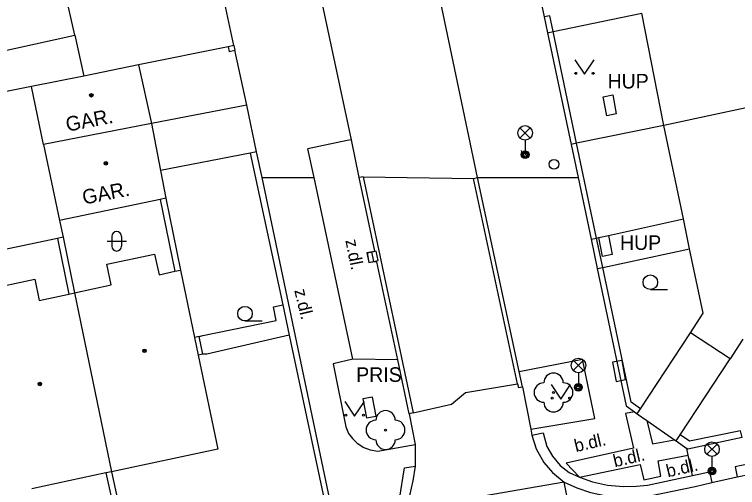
# Model space of a CAD drawing. Extents: x -596229 to -595156, y -1161237 to -1159376.
# Drawn here: x -595834.73 to -595797.54, y -1160999.35 to -1160975 of the extents above; entities that cross this region are included whole.
import ezdxf

# ---------------------------------------------------------------- set-up
doc = ezdxf.new("R2010")
doc.units = 0
for name, color, linetype in [('DOP - kresba z DSPS bez souradnic', 7, 'Continuous'), ('DOP - rozhrani ploch obecne', 7, 'Continuous'), ('Level 22', 7, 'Continuous'), ('Level 24', 7, 'Continuous'), ('Level 27', 7, 'Continuous'), ('Level 28', 7, 'Continuous'), ('Level 33', 7, 'Continuous'), ('Level 36', 7, 'Continuous'), ('Level 39', 7, 'Continuous'), ('plynovod - povrch.  znaky - PRIS skut. velikost', 7, 'Continuous'), ('Specificka linie pasportu komunikaci', 7, 'Continuous'), ('TM - budovy zdene_ betonove - VP', 7, 'Continuous'), ('TM - chodniky - VP', 7, 'Continuous'), ('TM - komunikace - VP', 7, 'Continuous'), ('TM - letecke snimky - pomocna linie', 7, 'Continuous'), ('TM - plot drateny_ kovovy - VP', 7, 'Continuous'), ('TM - podezdivka plotu - VP', 7, 'Continuous'), ('TM - popis objektu', 7, 'Continuous'), ('TM - popis povrchu', 7, 'Continuous'), ('TM - rozhrani mezi zpev. plochami mezi sebou - VP', 7, 'Continuous'), ('TM - rozhrani ploch obecne - VP', 7, 'Continuous'), ('TM - vjezd na pozemek', 7, 'Continuous'), ('TM - zabradli - VP', 7, 'Continuous')]:
    doc.layers.add(name, color=color, linetype=linetype)

msp = doc.modelspace()

# ---------------------------------------------------------------- linework, layer by layer
at = {"layer": 'DOP - kresba z DSPS bez souradnic'}
msp.add_lwpolyline([(-595832.52, -1160986.53), (-595831.93, -1160989.39)], dxfattribs=at)
at = {"layer": 'DOP - rozhrani ploch obecne'}
for points in [[(-595833.85, -1160978.71), (-595835.23, -1160978.99)], [(-595832.41, -1160985.61), (-595832.23, -1160986.47)], [(-595832.52, -1160986.53), (-595837.52, -1160987.57)], [(-595832.23, -1160986.47), (-595832.52, -1160986.53)], [(-595832.23, -1160986.47), (-595831.64, -1160989.33)]]:
    msp.add_lwpolyline(points, dxfattribs=at)
at = {"layer": 'Level 22'}
for centre in [(-595807, -1160994.46), (-595815.64, -1160996.39)]:
    msp.add_circle(centre, 0.05, dxfattribs=at)
for centre, start, end in [((-595807, -1160993.96), 0, 180), ((-595807.5, -1160994.46), 90, 270), ((-595806.5, -1160994.46), 270, 90), ((-595807, -1160994.96), 180, 0), ((-595815.64, -1160995.89), 0, 180), ((-595816.14, -1160996.39), 90, 270), ((-595815.14, -1160996.39), 270, 90), ((-595815.64, -1160996.89), 180, 0)]:
    msp.add_arc(centre, 0.5, start, end, dxfattribs=at)
at = {"layer": 'Level 24'}
for points in [[(-595803.968, -1160992.905), (-595803.783, -1160993.888), (-595803.292, -1160993.795), (-595803.477, -1160992.812)], [(-595816.809, -1160994.786), (-595816.622, -1160995.768), (-595816.13, -1160995.674), (-595816.318, -1160994.692)]]:
    msp.add_lwpolyline(points, close=True, dxfattribs=at)
at = {"layer": 'Level 27'}
msp.add_line((-595816.36, -1160987.225), (-595816.26, -1160987.715), dxfattribs=at)
msp.add_lwpolyline([(-595816.605, -1160987.275), (-595816.505, -1160987.765), (-595816.015, -1160987.665), (-595816.115, -1160987.175)], close=True, dxfattribs=at)
at = {"layer": 'Level 28'}
msp.add_circle((-595806.98, -1160982.71), 0.25, dxfattribs=at)
at = {"layer": 'Level 33'}
for p, q in [((-595808.725, -1160981.36), (-595808.195, -1160980.83)), ((-595808.725, -1160980.83), (-595808.195, -1160981.36)), ((-595808.46, -1160981.47), (-595808.46, -1160982.22)), ((-595805.985, -1160993.33), (-595805.455, -1160992.8)), ((-595805.985, -1160992.8), (-595805.455, -1160993.33)), ((-595805.72, -1160993.44), (-595805.72, -1160994.19)), ((-595799.115, -1160997.64), (-595798.585, -1160997.11)), ((-595799.115, -1160997.11), (-595798.585, -1160997.64)), ((-595798.85, -1160997.75), (-595798.85, -1160998.5))]:
    msp.add_line(p, q, dxfattribs=at)
for centre, radius in [((-595808.46, -1160981.095), 0.375), ((-595808.46, -1160982.22), 0.2), ((-595808.46, -1160982.22), 0.145), ((-595808.46, -1160982.22), 0.0876), ((-595805.72, -1160993.065), 0.375), ((-595805.72, -1160994.19), 0.2), ((-595805.72, -1160994.19), 0.145), ((-595805.72, -1160994.19), 0.0876), ((-595798.85, -1160997.375), 0.375), ((-595798.85, -1160998.5), 0.2), ((-595798.85, -1160998.5), 0.145), ((-595798.85, -1160998.5), 0.0876)]:
    msp.add_circle(centre, radius, dxfattribs=at)
at = {"layer": 'Level 36'}
for p, q in [((-595829.716, -1160986.426), (-595829.716, -1160986.926)), ((-595829.216, -1160986.426), (-595829.216, -1160986.926)), ((-595829.966, -1160986.676), (-595828.966, -1160986.676)), ((-595802.02, -1160989.155), (-595801.145, -1160989.155)), ((-595822.87, -1160990.775), (-595821.995, -1160990.775))]:
    msp.add_line(p, q, dxfattribs=at)
for points in [[(-595805.91, -1160977.33), (-595805.41, -1160978.08), (-595804.91, -1160977.33)], [(-595807.12, -1160994.05), (-595806.62, -1160994.8), (-595806.12, -1160994.05)], [(-595817.73, -1160994.92), (-595817.23, -1160995.67), (-595816.73, -1160994.92)]]:
    msp.add_lwpolyline(points, dxfattribs=at)
for centre, radius in [((-595805.86, -1160978.03), 0.05), ((-595804.961, -1160978.03), 0.05), ((-595802.02, -1160988.78), 0.375), ((-595822.87, -1160990.4), 0.375), ((-595807.07, -1160994.75), 0.05), ((-595806.171, -1160994.75), 0.05), ((-595817.68, -1160995.62), 0.05), ((-595816.781, -1160995.62), 0.05)]:
    msp.add_circle(centre, radius, dxfattribs=at)
for centre, start, end in [((-595829.466, -1160986.426), 0, 180), ((-595829.466, -1160986.926), 180, 0)]:
    msp.add_arc(centre, 0.25, start, end, dxfattribs=at)
at = {"layer": 'Level 39'}
for centre, radius in [((-595830.77, -1160979.16), 0.09), ((-595830.77, -1160979.16), 0.0398), ((-595830.03, -1160982.66), 0.09), ((-595830.03, -1160982.66), 0.0398), ((-595828.04, -1160992.31), 0.09), ((-595828.04, -1160992.31), 0.0398), ((-595833.42, -1160994.02), 0.09), ((-595833.42, -1160994.02), 0.0398)]:
    msp.add_circle(centre, radius, dxfattribs=at)
at = {"layer": 'plynovod - povrch.  znaky - PRIS skut. velikost'}
for points in [[(-595804.26, -1160980.22), (-595804.44, -1160979.24), (-595803.95, -1160979.14), (-595803.77, -1160980.12), (-595804.26, -1160980.22)], [(-595804.67, -1160986.48), (-595804.18, -1160986.38)], [(-595804.48, -1160987.46), (-595804.67, -1160986.48)], [(-595804.18, -1160986.38), (-595803.99, -1160987.36), (-595804.48, -1160987.46)]]:
    msp.add_lwpolyline(points, dxfattribs=at)
at = {"layer": 'Specificka linie pasportu komunikaci'}
for points in [[(-595821.99, -1160983.4), (-595819.31, -1160983.4)], [(-595816.79, -1160983.36), (-595811.11, -1160983.44)], [(-595810.91, -1160983.4), (-595810.37, -1160983.4), (-595807.43, -1160983.4), (-595805.74, -1160983.4)], [(-595804.18, -1160986.38), (-595800.32, -1160985.52)], [(-595805.07, -1160986.57), (-595804.79, -1160986.51)], [(-595804.79, -1160986.51), (-595804.67, -1160986.48)], [(-595804.47, -1160988.02), (-595800, -1160987.06)], [(-595804.76, -1160988.08), (-595804.47, -1160988.02)], [(-595814.22, -1160995.5), (-595812.25, -1160995.06), (-595811.52, -1160994.45), (-595808.85, -1160994.02)], [(-595799.85, -1160998.73), (-595800, -1160998.014), (-595800.07, -1160997.68)], [(-595806.45, -1160999.08), (-595814.68, -1161000.49)], [(-595804.43, -1161009.24), (-595806.45, -1160999.08)]]:
    msp.add_lwpolyline(points, dxfattribs=at)
at = {"layer": 'TM - budovy zdene_ betonove - VP'}
for points in [[(-595831.63, -1160976.06), (-595832.12, -1160973.85)], [(-595801.32, -1160980.71), (-595802.46, -1160974.93)], [(-595835.68, -1160976.96), (-595831.63, -1160976.06)], [(-595828.35, -1160977.6), (-595831.16, -1160978.17)], [(-595828.35, -1160977.6), (-595827.68, -1160980.62)], [(-595831.16, -1160978.17), (-595833.85, -1160978.71)], [(-595833.23, -1160981.7), (-595833.85, -1160978.71)], [(-595792.7, -1160978.87), (-595801.32, -1160980.71)], [(-595827.68, -1160980.62), (-595833.23, -1160981.7)], [(-595827.68, -1160980.62), (-595827.21, -1160983.03)], [(-595800.32, -1160985.52), (-595801.32, -1160980.71)], [(-595833.23, -1160981.7), (-595832.41, -1160985.61)], [(-595827.21, -1160983.03), (-595826.94, -1160984.46)], [(-595827.23, -1160984.52), (-595832.41, -1160985.61)], [(-595826.94, -1160984.46), (-595827.23, -1160984.52)], [(-595800, -1160987.06), (-595800.32, -1160985.52)], [(-595799.31, -1160990.38), (-595800, -1160987.06)], [(-595829.97, -1160987.85), (-595827.52, -1160987.34)], [(-595827.52, -1160987.34), (-595827.29, -1160988.4)], [(-595829.75, -1160988.92), (-595829.97, -1160987.85)], [(-595827.29, -1160988.4), (-595826.47, -1160988.22)], [(-595826.47, -1160988.22), (-595826.18, -1160988.16)], [(-595826.18, -1160988.16), (-595825.46, -1160991.62)], [(-595836.26, -1160989.17), (-595833.68, -1160988.63)], [(-595833.68, -1160988.63), (-595833.45, -1160989.72)], [(-595831.64, -1160989.33), (-595829.75, -1160988.92)], [(-595833.45, -1160989.72), (-595831.93, -1160989.39)], [(-595831.93, -1160989.39), (-595831.64, -1160989.33)], [(-595831.64, -1160989.33), (-595829.73, -1160998.54)], [(-595799.96, -1160991.39), (-595799.31, -1160990.38)], [(-595797.91, -1160992.72), (-595799.96, -1160991.39)], [(-595825.46, -1160991.62), (-595825.27, -1160992.53)], [(-595797.26, -1160991.72), (-595797.91, -1160992.72)], [(-595825.27, -1160992.53), (-595824.27, -1160997.38)], [(-595824.27, -1160997.38), (-595829.73, -1160998.54)], [(-595830.02, -1160998.6), (-595833.84, -1160999.41)], [(-595829.73, -1160998.54), (-595830.02, -1160998.6)]]:
    msp.add_lwpolyline(points, dxfattribs=at)
at = {"layer": 'TM - chodniky - VP'}
for points in [[(-595822.78, -1160979.67), (-595823.39, -1160976.84)], [(-595822.27, -1160982.07), (-595822.78, -1160979.67)], [(-595802.52, -1160995.3), (-595799.96, -1160991.39)], [(-595817.33, -1160992.75), (-595818.34, -1160992.98), (-595817.68, -1160996.23), (-595817.54, -1160996.57), (-595817.34, -1160996.83), (-595817.1, -1160997.06), (-595816.75, -1160997.29), (-595816.43, -1160997.41), (-595816.04, -1160997.48), (-595814.11, -1160997.13)], [(-595808.16, -1160996.35), (-595804.88, -1160995.8), (-595805.51, -1160992.75)], [(-595800.49, -1160996.63), (-595797.91, -1160992.72)], [(-595802.69, -1160995.55), (-595802.52, -1160995.3)], [(-595800.7, -1160996.95), (-595800.49, -1160996.63)]]:
    msp.add_lwpolyline(points, dxfattribs=at)
at = {"layer": 'TM - komunikace - VP'}
for points in [[(-595817.4, -1160981.45), (-595819.2, -1160973.01)], [(-595810.91, -1160983.4), (-595812.97, -1160973.56)], [(-595817.4, -1160981.45), (-595817.61, -1160981.49), (-595819.63, -1160981.91)], [(-595819.31, -1160983.4), (-595819.63, -1160981.91)], [(-595817.33, -1160992.75), (-595819.31, -1160983.4)], [(-595808.76, -1160993.38), (-595810.91, -1160983.4)], [(-595815.01, -1160992.78), (-595817.33, -1160992.75)], [(-595814.43, -1160995.55), (-595815.01, -1160992.78)], [(-595808.59, -1160994.16), (-595808.76, -1160993.38)], [(-595808.59, -1160994.16), (-595808.16, -1160996.35)], [(-595814.43, -1160995.55), (-595814.11, -1160997.13)], [(-595808.16, -1160996.35), (-595808.11, -1160996.65)], [(-595808.11, -1160996.65), (-595807.89, -1160997.35), (-595807.5, -1160998.06), (-595807.06, -1160998.58), (-595806.45, -1160999.08)], [(-595814.11, -1160997.13), (-595814.12, -1160998.25)], [(-595797.56, -1160998.79), (-595796.89, -1160998.66), (-595791.5, -1160997.54), (-595790.81, -1160997.39)], [(-595814.12, -1160998.25), (-595814.23, -1160999), (-595814.41, -1160999.76), (-595814.68, -1161000.49)], [(-595798.85, -1160999.09), (-595797.56, -1160998.79)], [(-595806.45, -1160999.08), (-595805.8, -1160999.37), (-595805.1, -1160999.6), (-595804.27, -1160999.78), (-595803.36, -1160999.86), (-595802.64, -1160999.84), (-595802.05, -1160999.77), (-595799.72, -1160999.29), (-595798.85, -1160999.09)]]:
    msp.add_lwpolyline(points, dxfattribs=at)
at = {"layer": 'TM - letecke snimky - pomocna linie'}
for points in [[(-595831.63, -1160976.06), (-595831.16, -1160978.17)], [(-595822.6, -1160982.14), (-595827.21, -1160983.03)], [(-595825.23, -1160991.57), (-595825.04, -1160991.53), (-595821.26, -1160990.76), (-595821.4, -1160990.05), (-595820.93, -1160989.95)], [(-595825.23, -1160991.57), (-595825.46, -1160991.62)], [(-595825.04, -1160992.48), (-595825.23, -1160991.57)], [(-595820.6, -1160991.51), (-595824.84, -1160992.49), (-595825.04, -1160992.48)], [(-595825.04, -1160992.48), (-595825.27, -1160992.53)], [(-595808.76, -1160993.38), (-595805.51, -1160992.75)]]:
    msp.add_lwpolyline(points, dxfattribs=at)
at = {"layer": 'TM - plot drateny_ kovovy - VP'}
for points in [[(-595807.02, -1160975.88), (-595807.19, -1160975.07), (-595807.48, -1160975.13)], [(-595805.81, -1160981.63), (-595807.02, -1160975.88)], [(-595823.73, -1160976.66), (-595823.68, -1160976.9), (-595823.39, -1160976.84)], [(-595804.79, -1160986.51), (-595805.81, -1160981.63)], [(-595822.6, -1160982.14), (-595820.93, -1160989.95)], [(-595804.47, -1160988.02), (-595804.79, -1160986.51)], [(-595802.52, -1160995.3), (-595803.01, -1160994.96), (-595804.47, -1160988.02)], [(-595820.93, -1160989.95), (-595820.6, -1160991.51)], [(-595820.6, -1160991.51), (-595818.59, -1161000.92), (-595825.65, -1161002.44)], [(-595797.3, -1160996.78), (-595797.38, -1160996.43), (-595800.01, -1160996.97), (-595800.49, -1160996.63)], [(-595830.02, -1160998.6), (-595829.01, -1161003.14)]]:
    msp.add_lwpolyline(points, dxfattribs=at)
at = {"layer": 'TM - podezdivka plotu - VP'}
for points in [[(-595807.48, -1160975.13), (-595807.31, -1160975.94)], [(-595807.31, -1160975.94), (-595806.1, -1160981.69)], [(-595823.44, -1160976.6), (-595823.39, -1160976.84)], [(-595806.1, -1160981.69), (-595805.74, -1160983.4)], [(-595822.27, -1160982.07), (-595822.6, -1160982.14)], [(-595821.99, -1160983.4), (-595822.27, -1160982.07)], [(-595818.35, -1161000.7), (-595821.99, -1160983.4)], [(-595805.74, -1160983.4), (-595805.07, -1160986.57)], [(-595805.07, -1160986.57), (-595804.76, -1160988.08)], [(-595804.76, -1160988.08), (-595803.27, -1160995.15), (-595802.83, -1160995.46)], [(-595802.83, -1160995.46), (-595802.69, -1160995.55)], [(-595800.7, -1160996.95), (-595800.15, -1160997.34)], [(-595797.3, -1160996.78), (-595800.09, -1160997.38), (-595800.15, -1160997.34)], [(-595829.73, -1160998.54), (-595828.75, -1161003.1)]]:
    msp.add_lwpolyline(points, dxfattribs=at)
at = {"layer": 'TM - rozhrani mezi zpev. plochami mezi sebou - VP'}
for points in [[(-595816.99, -1160983.4), (-595817.4, -1160981.45)], [(-595816.79, -1160983.36), (-595816.99, -1160983.4)], [(-595815.01, -1160992.78), (-595816.09, -1160987.73), (-595816.49, -1160987.77), (-595816.56, -1160987.27), (-595816.19, -1160987.19), (-595816.99, -1160983.4)], [(-595816.79, -1160983.36), (-595814.22, -1160995.5)], [(-595811.11, -1160983.44), (-595810.91, -1160983.4)], [(-595808.85, -1160994.02), (-595811.11, -1160983.44)], [(-595808.85, -1160994.02), (-595808.81, -1160994.2), (-595808.59, -1160994.16)], [(-595814.22, -1160995.5), (-595814.43, -1160995.55)], [(-595802.83, -1160995.46), (-595803.29, -1160995.54), (-595802.88, -1160997.33), (-595806.35, -1160998.1), (-595805.67, -1160998.81)], [(-595802.2, -1160995.9), (-595801.91, -1160997.1), (-595800.77, -1160996.9)], [(-595808.11, -1160996.65), (-595807.53, -1160996.53), (-595807.34, -1160997.23), (-595807.05, -1160997.73), (-595806.65, -1160998.21), (-595806.2, -1160998.58), (-595805.67, -1160998.81)], [(-595800.07, -1160997.68), (-595800.15, -1160997.34)], [(-595805.67, -1160998.81), (-595802.54, -1160998.17), (-595802.35, -1160998.96), (-595801.48, -1160998.76), (-595801.62, -1160997.98), (-595800.07, -1160997.68)], [(-595797.01, -1160998.15), (-595797.66, -1160998.29), (-595797.56, -1160998.79)], [(-595805.67, -1160998.81), (-595804.99, -1160999.05), (-595804.22, -1160999.22), (-595803.4, -1160999.29), (-595802.74, -1160999.28), (-595802.16, -1160999.22), (-595799.85, -1160998.73)], [(-595799.85, -1160998.73), (-595798.97, -1160998.54), (-595798.85, -1160999.09)]]:
    msp.add_lwpolyline(points, dxfattribs=at)
at = {"layer": 'TM - rozhrani ploch obecne - VP'}
for points in [[(-595807.02, -1160975.88), (-595802.46, -1160974.93)], [(-595807.31, -1160975.94), (-595807.02, -1160975.88)], [(-595823.73, -1160976.66), (-595828.35, -1160977.6)], [(-595823.44, -1160976.6), (-595823.73, -1160976.66)], [(-595822.78, -1160979.67), (-595827.68, -1160980.62)], [(-595801.32, -1160980.71), (-595805.81, -1160981.63)], [(-595805.81, -1160981.63), (-595806.1, -1160981.69)], [(-595827.23, -1160984.52), (-595826.47, -1160988.22)], [(-595826.94, -1160984.46), (-595826.18, -1160988.16)], [(-595818.35, -1161000.7), (-595814.93, -1160999.95), (-595814.67, -1160998.34), (-595814.12, -1160998.25)]]:
    msp.add_lwpolyline(points, dxfattribs=at)
at = {"layer": 'TM - vjezd na pozemek'}
for points in [[(-595807.98, -1160972.76), (-595807.48, -1160975.13)], [(-595823.44, -1160976.6), (-595823.96, -1160974.18)], [(-595802.69, -1160995.55), (-595802.2, -1160995.9)], [(-595802.2, -1160995.9), (-595800.77, -1160996.9)], [(-595800.77, -1160996.9), (-595800.7, -1160996.95)]]:
    msp.add_lwpolyline(points, dxfattribs=at)
at = {"layer": 'TM - zabradli - VP'}
msp.add_lwpolyline([(-595808.66, -1160982), (-595808.58, -1160982.35)], dxfattribs=at)

# ---------------------------------------------------------------- texts
at = {"layer": 'TM - popis objektu'}
for s, p in [('HUP', (-595804.22, -1160978.81)), ('HUP', (-595803.58, -1160987.12)), ('PRIS', (-595817.15, -1160993.91))]:
    msp.add_text(s, height=0.75, dxfattribs=at).set_placement(p)
for p in [(-595832.01, -1160981.04), (-595831.16, -1160984.79)]:
    msp.add_text('GAR.', height=0.75, rotation=11.03, dxfattribs=at).set_placement(p)
at = {"layer": 'TM - popis povrchu'}
for s, rotation, p in [('z.dl.', 281.31, (-595817.71, -1160986.63)), ('z.dl.', 283.49, (-595820.34, -1160989.2)), ('b.dl.', 13.11, (-595805.85, -1160997.53)), ('b.dl.', 13.11, (-595803.85, -1160998.31)), ('b.dl.', 13.11, (-595801.12, -1160998.83))]:
    msp.add_text(s, height=0.65, rotation=rotation, dxfattribs=at).set_placement(p)

doc.saveas('drawing.dxf')
